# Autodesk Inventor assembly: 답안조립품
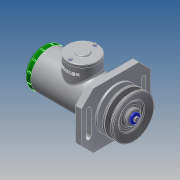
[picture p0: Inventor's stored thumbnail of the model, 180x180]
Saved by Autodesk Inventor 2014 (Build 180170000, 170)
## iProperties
Created: 2017-10
Part Number: 답안조립품
Document SubType Name: Assembly
Designer: kb542-14
Author: kb542-14
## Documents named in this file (20)
- C:\Users\kb542-14\Desktop\471007V1033\답안조립품.iam
- C:\Users\kb542-14\Desktop\471007V1033\본체.ipt
- C:\Users\kb542-14\Desktop\471007V1033\축.ipt
- C:\Users\kb542-14\Desktop\471007V1033\키 4 x 4 x 18.ipt
- C:\Users\kb542-14\Desktop\471007V1033\베어링 15 x 35 x 11.ipt
- C:\Users\kb542-14\Desktop\471007V1033\부시1.ipt
- C:\Users\kb542-14\Desktop\471007V1033\멈춤링 15 x 1.ipt
- C:\Users\kb542-14\Desktop\471007V1033\오일 실 15 25 7.ipt
- C:\Users\kb542-14\Desktop\471007V1033\멈춤링 35x1.6.ipt
- C:\Users\kb542-14\Desktop\471007V1033\부시2.ipt
- C:\Users\kb542-14\Desktop\471007V1033\와셔 10x21.ipt
- C:\Users\kb542-14\Desktop\471007V1033\너트 M10.ipt
- C:\Users\kb542-14\Desktop\471007V1033\사이드 커버.ipt
- 사이드 커버.ipt
- C:\Users\kb542-14\Desktop\471007V1033\V-벨트풀리.ipt
- C:\Users\kb542-14\Desktop\471007V1033\와셔 4x16.ipt
- C:\Users\kb542-14\Desktop\471007V1033\볼트 M4 x 10.ipt
- C:\Users\kb542-14\Desktop\471007V1033\탑 커버.ipt
- C:\Users\kb542-14\Desktop\471007V1033\와셔 3x6.ipt
- C:\Users\kb542-14\Desktop\471007V1033\십자볼트 M3 x 10.ipt
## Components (2 placed, 2 different names)
1. V-벨트풀리:1
2. ISO 4017 M4 x 10:1
